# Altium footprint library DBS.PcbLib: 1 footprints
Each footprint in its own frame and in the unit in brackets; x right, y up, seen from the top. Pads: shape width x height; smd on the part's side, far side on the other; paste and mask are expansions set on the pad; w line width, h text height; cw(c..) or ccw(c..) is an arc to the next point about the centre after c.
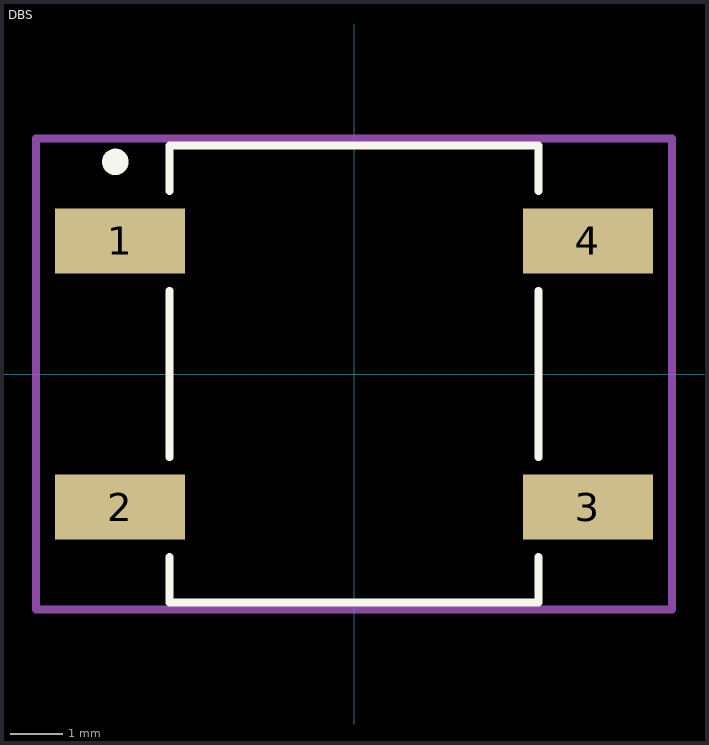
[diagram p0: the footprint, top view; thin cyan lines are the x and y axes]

## DBS [mm]
pads (4):
  rect 2.5x1.245 smd: 1(-4.483,2.55) 2(-4.483,-2.55) 3(4.483,-2.55) 4(4.483,2.55)
Top Overlay:
  circle w0.254: c-4.572,4.064 r0.127
  lines w0.152: -3.531,-3.505 -3.531,-4.381 3.531,-4.381 3.531,-3.505 ; -3.531,-1.595 -3.531,1.595 ; -3.531,3.505 -3.531,4.381 3.531,4.381 3.531,3.505 ; 3.531,-1.595 3.531,1.595
Mechanical 15:
  lines w0.152: -6.096,-4.508 -6.096,4.508 -3.658,4.508 3.658,4.508 6.096,4.508 6.096,-4.508 3.658,-4.508 -3.658,-4.508 -6.096,-4.508
3D body "SO4_DB-1S_MTC.step": height 2.59, standoff 0, extent -5.207,-4.254 5.207,4.254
